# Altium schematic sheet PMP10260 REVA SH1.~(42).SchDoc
size 431 x 279 mm; Date: Not shown in title block; ApprovedBy: Not shown in title block; CheckedBy: Not shown in title block; Author: Not shown in title block; CompanyName: Not shown in title block; Engineer: Not shown in title block; Organization: Not shown in title block; Address1: Not shown in title block; Address2: Not shown in title block; Address3: Not shown in title block; Address4: Not shown in title block; DocumentNumber: 1; Revision: Use project parameter SCH_Rev; SheetNumber: 1; SheetTotal: 4; PageSetup: Record=PageOptions|CenterHorizontal=True|CenterVertical=True|PrintScale=1.00|XCorrection=1.00|YCorrection=1.00|PrintKind=0|BorderSize=5000000|LeftOffset=0|BottomOffset=0|Orientation=2|PaperLength=1000|PaperWidth=1000|Scale=100|PaperSource=15|PrintQuality=600|MediaType=1|DitherType=10|PaperKind=Letter|PrintScaleMode=1
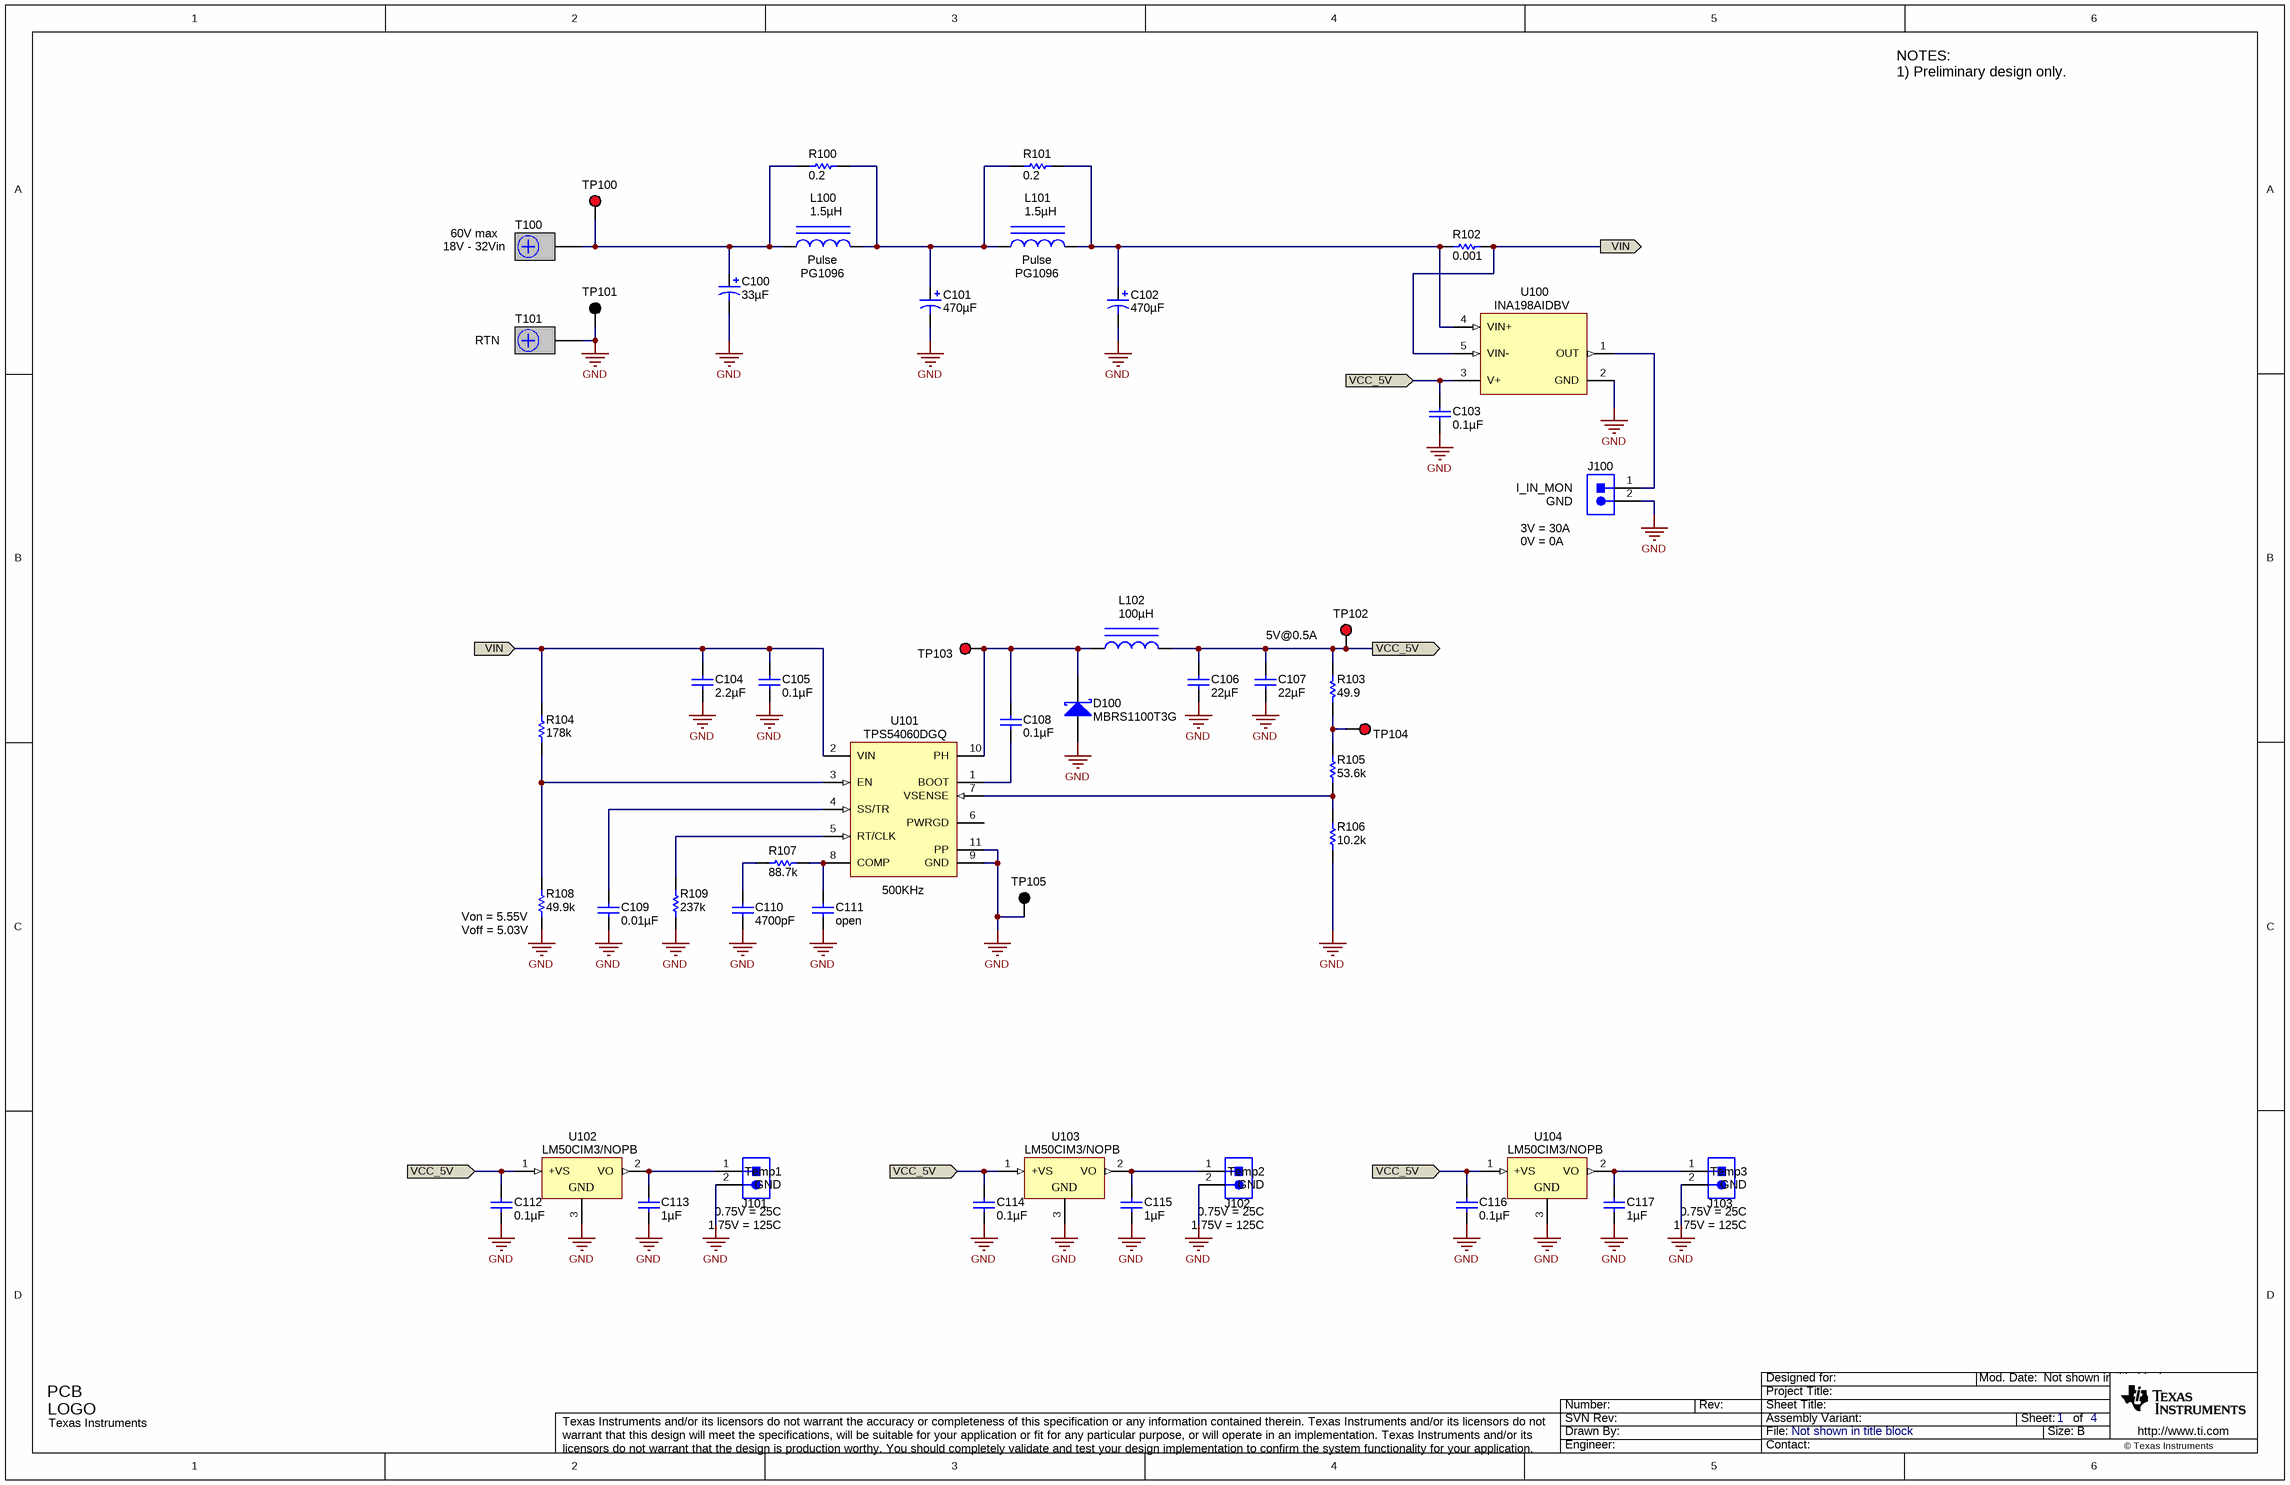
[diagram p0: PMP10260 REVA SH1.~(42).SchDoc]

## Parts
C100  ValueDisplayed: 33µF  [SXV_E12]  (hidden comment: 63SXV33M)
C101  ValueDisplayed: 470µF  [ZLH_1250x2500]  (hidden comment: 63ZLH470M12.5X25)
C102  ValueDisplayed: 470µF  [ZLH_1250x2500]  (hidden comment: 63ZLH470M12.5X25)
C103  ValueDisplayed: 0.1µF  [0603L]  (hidden comment: C1608X7R1H104K)
C104  ValueDisplayed: 2.2µF  [1210]  (hidden comment: GRM32ER72A225KA35L)
C105  ValueDisplayed: 0.1µF  [0603]  (hidden comment: GRM188R72A104KA35D)
C106  ValueDisplayed: 22µF  [1210]  (hidden comment: C3225X7R1C226M)
C107  ValueDisplayed: 22µF  [1210]  (hidden comment: C3225X7R1C226M)
C108  ValueDisplayed: 0.1µF  [0603L]  (hidden comment: C1608X7R1H104K)
C109  ValueDisplayed: 0.01µF  [0603]  (hidden comment: C1608X7R1H103K)
C110  ValueDisplayed: 4700pF  [0603]  (hidden comment: C1608C0G1H472J)
C111  ValueDisplayed: open  [0603L]
C112  ValueDisplayed: 0.1µF  [0603L]  (hidden comment: C1608X7R1H104K)
C113  ValueDisplayed: 1µF  [0603L]  (hidden comment: C1608X7R1E105K080AB)
C114  ValueDisplayed: 0.1µF  [0603L]  (hidden comment: C1608X7R1H104K)
C115  ValueDisplayed: 1µF  [0603L]  (hidden comment: C1608X7R1E105K080AB)
C116  ValueDisplayed: 0.1µF  [0603L]  (hidden comment: C1608X7R1H104K)
C117  ValueDisplayed: 1µF  [0603L]  (hidden comment: C1608X7R1E105K080AB)
D100  MBRS1100T3G  [SMB]
J100  PEC02SAAN  [CONN_PEC02SAAN]  (value not drawn)
J101  PEC02SAAN  [CONN_PEC02SAAN]  (value not drawn)
J102  PEC02SAAN  [CONN_PEC02SAAN]  (value not drawn)
J103  PEC02SAAN  [CONN_PEC02SAAN]  (value not drawn)
L100  ValueDisplayed: 1.5µH  [SER2918]
L101  ValueDisplayed: 1.5µH  [SER2918]
L102  ValueDisplayed: 100µH  [MSS1048]  (hidden comment: MSS1048-104MLB)
Logo100  Texas Instruments  [TI_Stacked_Overlay_Small]  (no BOM)
R100  value 0.2  [2512M]  (hidden comment: WSL2512R2000FEA)
R101  value 0.2  [2512M]  (hidden comment: WSL2512R2000FEA)
R102  value 0.001  [CSS2725_0005]  (hidden comment: CSS2725FT1L00)
R103  value 49.9  [0603]  (hidden comment: CRCW060349R9FKEA)
R104  value 178k  [0603]  (hidden comment: CRCW0603178KFKEA)
R105  value 53.6k  [0603]  (hidden comment: CRCW060353K6FKEA)
R106  value 10.2k  [0603]  (hidden comment: CRCW060310K2FKEA)
R107  value 88.7k  [0603]  (hidden comment: CRCW060388K7FKEA)
R108  value 49.9k  [0603]  (hidden comment: CRCW060349K9FKEA)
R109  value 237k  [0603]  (hidden comment: CRCW0603237KFKEA)
T100  CB35-36-CY  [CB35-36-CY]  (value not drawn)
T101  CB35-36-CY  [CB35-36-CY]  (value not drawn)
TP100  5010  [Keystone5010]  (value not drawn)
TP101  5011  [Keystone5011]  (value not drawn)
TP102  5010  [Keystone5010]  (value not drawn)
TP103  5010  [Keystone5010]  (value not drawn)
TP104  5010  [Keystone5010]  (value not drawn)
TP105  5011  [Keystone5011]  (value not drawn)
U100  INA198AIDBV  [DBV0005A_N]
U101  TPS54060DGQ  [DGQ0010D_N]
U102  LM50CIM3/NOPB  [MF03A_N]
U103  LM50CIM3/NOPB  [MF03A_N]
U104  LM50CIM3/NOPB  [MF03A_N]

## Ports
VCC_5V, VIN

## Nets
GND: C100.2(-) C101.2(-) C102.2(-) C103.2 C104.2 C105.2 C106.2 C107.2 C109.2 C110.2 C111.2 C112.2 C113.2 C114.2 C115.2 C116.2 C117.2 D100.2(A) J100.2 J101.2 J102.2 J103.2 R106.1 R108.1 R109.1 T101.1 TP101.1 TP105.1 U100.2(GND) U101.9(GND) U101.11(PP) U102.3(GND) U103.3(GND) U104.3(GND)
VCC_5V: C103.1 C106.1 C107.1 C112.1 C114.1 C116.1 L102.2 R103.2 TP102.1 U100.3(V+) U102.1(+VS) U103.1(+VS) U104.1(+VS) ; port VCC_5V
VIN: C104.1 C105.1 R102.2 R104.2 U100.5(VIN-) U101.2(VIN) ; port VIN
NetC100_1: C100.1(+) L100.1 R100.1 T100.1 TP100.1
NetC101_1: C101.1(+) L100.2 L101.1 R100.2 R101.1
NetC102_1: C102.1(+) L101.2 R101.2 R102.1 U100.4(VIN+)
NetC108_1: C108.1 D100.1(K) L102.1 TP103.1 U101.10(PH)
NetC108_2: C108.2 U101.1(BOOT)
NetC109_1: C109.1 U101.4(SS/TR)
NetC110_1: C110.1 R107.2
NetC111_1: C111.1 R107.1 U101.8(COMP)
NetC113_1: C113.1 J101.1 U102.2(VO)
NetC115_1: C115.1 J102.1 U103.2(VO)
NetC117_1: C117.1 J103.1 U104.2(VO)
NetJ100_1: J100.1 U100.1(OUT)
NetR103_1: R103.1 R105.2 TP104.1
NetR104_1: R104.1 R108.2 U101.3(EN)
NetR105_1: R105.1 R106.2 U101.7(VSENSE)
NetR109_2: R109.2 U101.5(RT/CLK)

Not connected (* = marked no-connect by the designer): U101 6(PWRGD)

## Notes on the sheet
- NOTES:
  1) Preliminary design only.
- 60V max
- (near T100) 18V - 32Vin
- (near L100) Pulse
- (near L100) PG1096
- (near L101) Pulse
- (near L101) PG1096
- RTN
- (near J100) I_IN_MON
- (near J100) GND
- (near J100) 3V = 30A
- 0V = 0A
- 5V@0.5A
- (near U101) 500KHz
- (near R108) Von = 5.55V
- (near R108) Voff = 5.03V
- (near J101) Temp1
- (near J102) Temp2
- (near J103) Temp3
- (near J101) 0.75V = 25C
- (near J101) 1.75V = 125C
- (near J101) GND
- (near J102) 0.75V = 25C
- (near J102) 1.75V = 125C
- (near J102) GND
- (near J103) 0.75V = 25C
- (near J103) 1.75V = 125C
- (near J103) GND

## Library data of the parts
C100 = 63SXV33M: CAP, OS-CON, 33uF, 63V, +/-20%, 0.025 ohm, 8.0x11.9mm SMD; Manufacturer: Panasonic; Polarized: Y; CompType: Capacitor; U/M: EA; Cap_F: 0.000033; Tolerance_%: 20; VDC_V: 63; ESR_Ohm: 0.025; IRMS_A: 2.95; TaMin_C: -55; TaMax_C: 105
C101 C102 = 63ZLH470M12.5X25: CAP, AL, 470uF, 63V, +/-20%, 0.043 ohm, TH; Manufacturer: Rubycon; Polarized: Y; CompType: Capacitor; U/M: EA; Cap_F: 0.00047; Tolerance_%: 20; VDC_V: 63; ESR_Ohm: 0.043; IRMS_A: 1.99; TaMin_C: -40; TaMax_C: 105
C103 C108 C112 C114 C116 = C1608X7R1H104K: CAP, CERM, 0.1uF, 50V, +/-10%, X7R, 0603; Manufacturer: TDK; Polarized: N; CompType: Capacitor; U/M: EA; Cap_F: 0.0000001; Tolerance_%: 10; ESR_Ohm: 0.017; Value1: 0.017 ohm; VDC_V: 50; TaMin_C: -55; TaMax_C: 125; Cap_Case: 0603
C104 = GRM32ER72A225KA35L: CAP, CERM, 2.2uF, 100V, +/-10%, X7R, 1210; Manufacturer: MuRata; Polarized: N; CompType: Capacitor; U/M: EA; Cap_F: 0.0000022; Tolerance_%: 10; ESR_Ohm: 0.007; Value1: 0.007 ohm; VDC_V: 100; IRMS_A: 4.4; TaMin_C: -55; TaMax_C: 125
C105 = GRM188R72A104KA35D: CAP, CERM, 0.1uF, 100V, +/-10%, X7R, 0603; Manufacturer: MuRata; Polarized: N; CompType: Capacitor; U/M: EA; Cap_F: 0.0000001; Tolerance_%: 10; Value1: Unknown; VDC_V: 100; TaMin_C: -55; TaMax_C: 125
C106 C107 = C3225X7R1C226M: CAP, CERM, 22uF, 16V, +/-20%, X7R, 1210; Manufacturer: TDK; Polarized: N; CompType: Capacitor; U/M: EA; Cap_F: 0.000022; Tolerance_%: 20; ESR_Ohm: 0.002; Value1: 0.002 ohm; VDC_V: 16; IRMS_A: 8.11; TaMin_C: -55; TaMax_C: 125
C109 = C1608X7R1H103K: CAP, CERM, 0.01uF, 50V, +/-10%, X7R, 0603; Manufacturer: TDK; Polarized: N; CompType: Capacitor; U/M: EA; Cap_F: 0.00000001; Tolerance_%: 10; ESR_Ohm: 0.0539; Value1: 0.0539 ohm; VDC_V: 50; TaMin_C: -55; TaMax_C: 125
C110 = C1608C0G1H332J: CAP, CERM, 4700pF, 50V, +/-5%, C0G/NP0, 0603; Manufacturer: TDK; Polarized: N; CompType: Capacitor; Value: 3300pF; U/M: EA; Cap_F: 0.0000000033; Tolerance_%: 5; ESR_Ohm: 0.0309; Value1: 0.0309 ohm; VDC_V: 50; TaMin_C: -55; TaMax_C: 125
C111 = C1608X7R1H104K: CAP, open, 0603; Polarized: N; CompType: Capacitor; U/M: EA; Cap_F: 0.0000001; Tolerance_%: 10; ESR_Ohm: 0.017; TempCo: X7R; TaMin_C: -55; TaMax_C: 125; Cap_Case: 0603
C113 C115 C117 = C1608X7R1E105K080AB: CAP, CERM, 1uF, 25V, +/-10%, X7R, 0603; Manufacturer: TDK; Polarized: N; CompType: Capacitor; U/M: EA; Cap_F: 0.000001; Tolerance_%: 10; Value1: Unknown; VDC_V: 25; TaMin_C: -55; TaMax_C: 125; Cap_Case: 0603
D100 = MBRS1100T3G: Diode, Schottky, 100V, 1A, SMB; Manufacturer: ON Semiconductor; U/M: EA; Vf_V: 0.75; Value2: 0.75V; Io_A: 1; Vr_V: 100; TJmax_C: 150; RJC_CperW: 22
J100-J103 = PEC02SAAN: Header, 100mil, 2x1, Tin, TH; Manufacturer: Sullins Connector Solutions; SymbolCreator: a0412235; U/M: EA
L100 L101 = SER2918H-332KL: Inductor, Shielded E Core, Ferrite, 3.3uH, 28A, 0.0026 ohm, SMD; Manufacturer: Pulse; Ind_H: 3.3E-6; Imax_A: 28; Irms: 28A @ 40C rise; Isat: 93.6A @ 30% inductance drop; DCR_ohm: 0.0026
L102 = MSS1048-104MLB: Inductor, Shielded Drum Core, Ferrite, 100uH, 1.36A, 0.25 ohm, SMD; Manufacturer: Coilcraft; Ind_H: 100.0E-6; Imax_A: 1.36; Irms: 1.48A @ 40C rise; Isat: 1.36A @ 30% inductance drop; DCR_ohm: 0.25
Logo100 = TI_Logo: Texas Instrument Corporate Signature; SymbolCreator: codlsc
R100 R101 = WSL2512R2000FEA: RES, 0.2 ohm, 1%, 1W, 2512; Manufacturer: Vishay-Dale; CompType: Resistor; Value_Code: R200; Tolerance_%: 1; VDC_V: 0.45; TempCo: 75 ppm/C; EIA_Code: E96; U/M: EA
R102 = CSS2725FTL500: RES, 0.001 ohm, 1%, 4W, RES_2725; Manufacturer: Stackpole Electronics Inc; CompType: Resistor; Res_ohm: 0.0005; Value_Code: R001; Tolerance_%: 1; Power_W: 4; TempCo: 50 ppm/C; U/M: EA
R103 = CRCW060349R9FKEA: RES, 49.9 ohm, 1%, 0.1W, 0603; Manufacturer: Vishay-Dale; CompType: Resistor; Value_Code: 49R9; Tolerance_%: 1; Power_W: 0.1; VDC_V: 75; TempCo: 100 ppm/C; EIA_Code: E96; U/M: EA
R104 = CRCW0603178KFKEA: RES, 178k ohm, 1%, 0.1W, 0603; Manufacturer: Vishay-Dale; CompType: Resistor; Res_ohm: 178000; Tolerance_%: 1; Power_W: 0.1; VDC_V: 75; TempCo: 100 ppm/C; EIA_Code: E96; U/M: EA
R105 = CRCW060353K6FKEA: RES, 53.6k ohm, 1%, 0.1W, 0603; Manufacturer: Vishay-Dale; CompType: Resistor; Res_ohm: 53600; Value_Code: 53k6; Tolerance_%: 1; Power_W: 0.1; VDC_V: 75; TempCo: 100 ppm/C; EIA_Code: E96; U/M: EA
R106 = CRCW060310K2FKEA: RES, 10.2k ohm, 1%, 0.1W, 0603; Manufacturer: Vishay-Dale; CompType: Resistor; Res_ohm: 10200; Value_Code: 10k2; Tolerance_%: 1; Power_W: 0.1; VDC_V: 75; TempCo: 100 ppm/C; EIA_Code: E96; U/M: EA
R107 = CRCW060388K7FKEA: RES, 88.7k ohm, 1%, 0.1W, 0603; Manufacturer: Vishay-Dale; CompType: Resistor; Res_ohm: 88700; Value_Code: 88k7; Tolerance_%: 1; Power_W: 0.1; VDC_V: 75; TempCo: 100 ppm/C; EIA_Code: E96; U/M: EA
R108 = CRCW060349K9FKEA: RES, 49.9k ohm, 1%, 0.1W, 0603; Manufacturer: Vishay-Dale; CompType: Resistor; Res_ohm: 49900; Value_Code: 49k9; Tolerance_%: 1; Power_W: 0.1; VDC_V: 75; TempCo: 100 ppm/C; EIA_Code: E96; U/M: EA
R109 = CRCW0603237KFKEA: RES, 237k ohm, 1%, 0.1W, 0603; Manufacturer: Vishay-Dale; CompType: Resistor; Res_ohm: 237000; Tolerance_%: 1; Power_W: 0.1; VDC_V: 75; TempCo: 100 ppm/C; EIA_Code: E96; U/M: EA
T100 T101 = CB35-36-CY: Terminal 50A Lug; Manufacturer: Panduit; SymbolCreator: crossc; CompType: Screw Terminal; U/M: EA
TP100 TP102-TP104 = 5010: Test Point, Multipurpose, Red, TH; Manufacturer: Keystone; CompType: Test Point Loop; U/M: EA
TP101 TP105 = 5011: Test Point, Multipurpose, Black, TH; Manufacturer: Keystone; CompType: Test Point Loop; U/M: EA
U100 = INA198AIDBV: CURRENT SHUNT MONITOR -16V to +80V Common-Mode Range, DBV0005A; Alternate Manufacturer: None; Manufacturer: Texas Instruments; SymbolCreator: a0411947; CompType: IC; U/M: EA
U101 = TPS54060DGQ: Buck Inverting Buck-Boost Step Down Regulator with 3.5 to 60 V Input and 0.8 to 58 V Output, -40 to 150 degC, 10-Pin MSOP-PowerPAD (DGQ), Green (RoHS & no Sb/Br); Manufacturer: Texas Instruments; Alternate Manufacturer: None; Alternate PartNumber: Equivalent; Duty Cycle(Max)(%): 98; Iout(Max)(A): 0.5; Iq(Typ)(mA): 0.116; Rating: Catalog; Regulated Outputs(#): 1; SubFamily: Step-Down Regulator; Switch Current Limit(Typ)(A): 0.6; Topology: Buck, Inverting Buck-Boost; Vin(Max)(V): 60; Vin(Min)(V): 3.5; Vout(Max)(V): 58; Vout(Min)(V): 0.8
U102-U104 = LM50CIM3/NOPB: Single-Supply Centigrade Temperature Sensor, 3-pin SOT-23, Pb-Free; Manufacturer: Texas Instruments; PackageTopMarking: T5C*XTT; PowerWise: N; CompType: Temp Sensor IC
